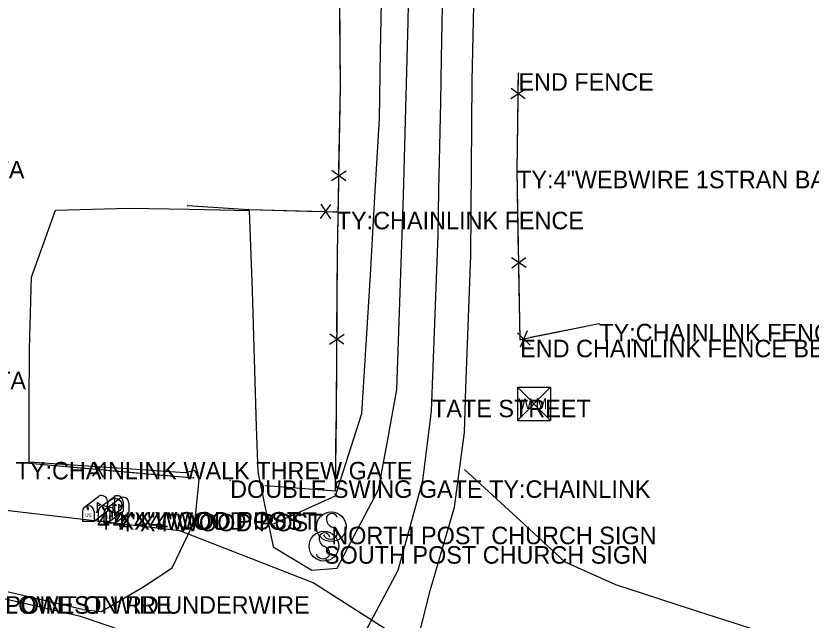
# Model space of a CAD drawing. Extents: x 1050807 to 1053552, y 395828 to 398415.
# Drawn here: x 1051813.5 to 1052040.5, y 398068.8 to 398241.2 of the extents above; entities that cross this region are included whole.
import ezdxf

# ---------------------------------------------------------------- set-up
doc = ezdxf.new("R2010")
doc.units = 0
for name, color, linetype in [('S_BUILDING_ANNOT', 7, 'Continuous'), ('S_EDGE_PAVEMENT', 7, 'Continuous'), ('S_ELECTRIC_UTILITIES_ANNOT', 7, 'Continuous'), ('S_FENCE', 7, 'Continuous'), ('S_FENCE_ANNOT', 7, 'Continuous'), ('S_GATE_ANNOT', 7, 'Continuous'), ('S_GRAVEL_ROAD', 7, 'Continuous'), ('S_MAILBOX', 7, 'Continuous'), ('S_MAILBOX_ANNOT', 7, 'Continuous'), ('S_MSC_PT_SYM', 7, 'Continuous'), ('S_PAVEMENT_CROWN', 7, 'Continuous'), ('S_SHOULDER', 7, 'Continuous'), ('S_SIGN', 7, 'Continuous'), ('S_SIGN_ANNOT', 7, 'Continuous'), ('S_SURVEY_TEXT_ANNOT', 7, 'Continuous'), ('S_UTILITY_POLE', 7, 'Continuous'), ('S_UTL_PT_SYM', 7, 'Continuous'), ('S_WATER_UTILITIES', 7, 'Continuous')]:
    doc.layers.add(name, color=color, linetype=linetype)

msp = doc.modelspace()

# ---------------------------------------------------------------- linework, layer by layer
at = {"layer": 'S_EDGE_PAVEMENT'}
for points in [[(1051934.63, 398023.1), (1051930.06, 398027.26), (1051929.8, 398038.82), (1051925.96, 398053.99), (1051931.83, 398077.54), (1051938.69, 398100.99), (1051941.54, 398122.27), (1051942, 398134.91), (1051942.46, 398147.55), (1051942.93, 398160.19), (1051943.39, 398172.83), (1051943.59, 398197.73), (1051943.79, 398222.64), (1051944.04, 398235.63), (1051944.3, 398248.63), (1051944.55, 398261.62), (1051944.81, 398274.62), (1051944.95, 398287.8), (1051945.09, 398300.98), (1051945.24, 398314.17), (1051945.38, 398327.35), (1051945.7, 398344.1), (1051946.02, 398360.85)], [(1051832.59, 398071.82), (1051837.82, 398071.26), (1051849.77, 398078.16), (1051858.11, 398083.68), (1051864.69, 398097.36), (1051865.79, 398108.89), (1051864.58, 398111.44), (1051861.82, 398110.77), (1051839.56, 398112.3), (1051817.29, 398113.82), (1051817.34, 398129.93), (1051817.39, 398146.04), (1051817.93, 398166.59), (1051824.83, 398185.78), (1051845.77, 398186.36), (1051862.94, 398186), (1051880.11, 398185.63), (1051880.93, 398162.71), (1051881.33, 398149.8), (1051881.73, 398136.89), (1051882.13, 398123.97), (1051882.54, 398111.06), (1051886.98, 398089.68), (1051898.02, 398083.02), (1051905.24, 398083.58), (1051911.15, 398094.8), (1051917.06, 398106.02), (1051919.65, 398120.3), (1051922.25, 398134.57), (1051922.72, 398148.4), (1051923.19, 398162.24), (1051923.67, 398176.07), (1051924.14, 398189.9), (1051924.81, 398214.72), (1051925.48, 398239.54), (1051926, 398264.45)], [(1051844.58, 398065.54), (1051831.93, 398069.76), (1051807.96, 398075.33)]]:
    msp.add_lwpolyline(points, dxfattribs=at)
at = {"layer": 'S_FENCE'}
for p, q in [((1051906.18, 398220.91), (1051905.81, 398265.54)), ((1051956.61, 398197), (1051956.97, 398224.83)), ((1051905.3, 398173.58), (1051906.18, 398220.91)), ((1051954.83, 398217.59), (1051958.96, 398220.41)), ((1051954.83, 398217.59), (1051958.96, 398220.41)), ((1051958.92, 398217.54), (1051954.86, 398220.46)), ((1051958.92, 398217.54), (1051954.86, 398220.46)), ((1051903.64, 398194.18), (1051907.79, 398196.97)), ((1051903.64, 398194.18), (1051907.79, 398196.97)), ((1051907.73, 398194.1), (1051903.69, 398197.05)), ((1051907.73, 398194.1), (1051903.69, 398197.05)), ((1051957.47, 398148.77), (1051956.61, 398197)), ((1051862.46, 398187.07), (1051879.97, 398185.9)), ((1051900.48, 398183.35), (1051903.45, 398187.38)), ((1051900.48, 398183.35), (1051903.45, 398187.38)), ((1051900.58, 398187.45), (1051903.35, 398183.28)), ((1051900.58, 398187.45), (1051903.35, 398183.28)), ((1051879.97, 398185.9), (1051905.1, 398185.29)), ((1051905, 398126.9), (1051905.3, 398173.58)), ((1051959.15, 398169.37), (1051955, 398172.16)), ((1051959.15, 398169.37), (1051955, 398172.16)), ((1051955.06, 398169.3), (1051959.1, 398172.24)), ((1051955.06, 398169.3), (1051959.1, 398172.24)), ((1051980.06, 398153.3), (1051957.47, 398148.77)), ((1051903.08, 398147.48), (1051907.2, 398150.32)), ((1051903.08, 398147.48), (1051907.2, 398150.32)), ((1051907.18, 398147.46), (1051903.1, 398150.35)), ((1051907.18, 398147.46), (1051903.1, 398150.35)), ((1051960.3, 398147.25), (1051956.69, 398150.7)), ((1051960.3, 398147.25), (1051956.69, 398150.7)), ((1051959.5, 398151.27), (1051957.49, 398146.69)), ((1051959.5, 398151.27), (1051957.49, 398146.69)), ((1051904.76, 398105.62), (1051905, 398126.9)), ((1051835.88, 398113.92), (1051838.38, 398109.59)), ((1051835.88, 398113.92), (1051838.38, 398109.59)), ((1051815.22, 398113.69), (1051864.2, 398109.36)), ((1051835.52, 398109.84), (1051838.74, 398113.67)), ((1051835.52, 398109.84), (1051838.74, 398113.67)), ((1051884.8, 398107.15), (1051904.76, 398105.62))]:
    msp.add_line(p, q, dxfattribs=at)
for points in [[(1051906.18, 398220.91), (1051906.01, 398240.91)], [(1051906.18, 398220.91), (1051906.01, 398240.91)], [(1051956.92, 398221), (1051956.97, 398224.83)], [(1051956.92, 398221), (1051956.97, 398224.83)], [(1051905.75, 398197.58), (1051906.18, 398220.91)], [(1051905.75, 398197.58), (1051906.18, 398220.91)], [(1051956.61, 398197), (1051956.87, 398217)], [(1051956.61, 398197), (1051956.87, 398217)], [(1051957.04, 398172.77), (1051956.61, 398197)], [(1051957.04, 398172.77), (1051956.61, 398197)], [(1051905.3, 398173.58), (1051905.67, 398193.58)], [(1051905.3, 398173.58), (1051905.67, 398193.58)], [(1051862.46, 398187.07), (1051879.97, 398185.9)], [(1051862.46, 398187.07), (1051879.97, 398185.9)], [(1051879.97, 398185.9), (1051899.97, 398185.41)], [(1051879.97, 398185.9), (1051899.97, 398185.41)], [(1051903.96, 398185.31), (1051905.1, 398185.29)], [(1051903.96, 398185.31), (1051905.1, 398185.29)], [(1051905.15, 398150.9), (1051905.3, 398173.58)], [(1051905.15, 398150.9), (1051905.3, 398173.58)], [(1051957.47, 398148.77), (1051957.11, 398168.77)], [(1051957.47, 398148.77), (1051957.11, 398168.77)], [(1051980.06, 398153.3), (1051960.45, 398149.37)], [(1051980.06, 398153.3), (1051960.45, 398149.37)], [(1051905, 398126.9), (1051905.13, 398146.9)], [(1051905, 398126.9), (1051905.13, 398146.9)], [(1051904.76, 398105.62), (1051904.98, 398125.62)], [(1051904.76, 398105.62), (1051904.98, 398125.62)], [(1051815.22, 398113.69), (1051835.14, 398111.93)], [(1051815.22, 398113.69), (1051835.14, 398111.93)], [(1051839.12, 398111.58), (1051864.2, 398109.36)], [(1051839.12, 398111.58), (1051864.2, 398109.36)], [(1051884.8, 398107.15), (1051904.72, 398105.62)], [(1051884.8, 398107.15), (1051904.72, 398105.62)]]:
    msp.add_lwpolyline(points, dxfattribs=at)
at = {"layer": 'S_GRAVEL_ROAD'}
for points in [[(1051920.21, 398327.61), (1051919.09, 398311.82), (1051919.87, 398290.35), (1051918.86, 398270.17), (1051917.86, 398250), (1051917.52, 398230.91), (1051917.19, 398211.82), (1051915.93, 398189.54), (1051914.68, 398167.26), (1051913.41, 398147.42), (1051912.15, 398127.59), (1051904.68, 398104.16), (1051886.45, 398095.96)], [(1051941.6, 398111.76), (1051957.6, 398097.06), (1051970.21, 398085.36), (1051984.67, 398078.88), (1052006.03, 398072.02), (1052027.38, 398065.17), (1052046.41, 398052.69), (1052065.44, 398040.21), (1052080.08, 398025.28), (1052094.72, 398010.35), (1052105.27, 397991.93), (1052108.07, 397979.7), (1052110.87, 397967.48), (1052113.67, 397955.25), (1052116.48, 397943.02), (1052122.03, 397920.87), (1052127.57, 397898.72), (1052130.86, 397881.88), (1052134.15, 397865.05), (1052139.91, 397846.05), (1052147.47, 397834.83)]]:
    msp.add_lwpolyline(points, dxfattribs=at)
at = {"layer": 'S_MAILBOX'}
for p, q in [((1051833.08, 398101.02), (1051837.21, 398104.13)), ((1051837.55, 398100.97), (1051841.69, 398104.07)), ((1051839.19, 398100.54), (1051843.33, 398103.64)), ((1051839.64, 398102.66), (1051839.64, 398099.94)), ((1051844.12, 398102.6), (1051844.12, 398099.89)), ((1051836.69, 398102.31), (1051836.69, 398099.6)), ((1051841.17, 398102.25), (1051841.17, 398099.54)), ((1051842.81, 398101.82), (1051842.81, 398099.11)), ((1051845.76, 398102.17), (1051845.76, 398099.46)), ((1051832.52, 398099.75), (1051832.52, 398097.03)), ((1051835.85, 398097.03), (1051839.64, 398099.94)), ((1051835.85, 398099.75), (1051835.85, 398097.03)), ((1051837, 398099.69), (1051837, 398096.98)), ((1051838.64, 398099.26), (1051838.64, 398096.55)), ((1051840.32, 398096.98), (1051844.12, 398099.89)), ((1051840.32, 398099.69), (1051840.32, 398096.98)), ((1051841.96, 398096.55), (1051845.76, 398099.46)), ((1051841.96, 398099.26), (1051841.96, 398096.55)), ((1051832.52, 398097.03), (1051835.85, 398097.03)), ((1051837, 398096.98), (1051840.32, 398096.98)), ((1051838.64, 398096.55), (1051841.96, 398096.55))]:
    msp.add_line(p, q, dxfattribs=at)
for points in [[(1051833.71, 398100.86), (1051833.93, 398100.73), (1051833.93, 398100.34), (1051834.23, 398100.34), (1051834.23, 398100.7), (1051834.04, 398100.95), (1051833.71, 398100.89)], [(1051836.69, 398102.31), (1051837.8, 398101.65), (1051836.69, 398101.3)], [(1051838.18, 398100.81), (1051838.4, 398100.67), (1051838.4, 398100.28), (1051838.71, 398100.28), (1051838.71, 398100.64), (1051838.51, 398100.89), (1051838.18, 398100.83)], [(1051839.82, 398100.38), (1051840.04, 398100.24), (1051840.04, 398099.85), (1051840.35, 398099.85), (1051840.35, 398100.21), (1051840.15, 398100.46), (1051839.82, 398100.4)], [(1051841.17, 398102.25), (1051842.27, 398101.59), (1051841.17, 398101.24)], [(1051842.81, 398101.82), (1051843.91, 398101.16), (1051842.81, 398100.81)]]:
    msp.add_lwpolyline(points, dxfattribs=at)
for centre, end in [((1051837.98, 398102.66), 117.5718), ((1051842.45, 398102.6), 117.5718), ((1051844.09, 398102.17), 117.5718), ((1051834.18, 398099.75), 180), ((1051838.66, 398099.69), 180), ((1051840.3, 398099.26), 180)]:
    msp.add_arc(centre, 1.66, 0, end, dxfattribs=at)
for centre in [(1051836.69, 398099.6), (1051841.17, 398099.54), (1051842.81, 398099.11)]:
    msp.add_ellipse(centre, major_axis=(0.145, 0.132), ratio=0.564646, dxfattribs=at)
at = {"layer": 'S_MSC_PT_SYM'}
for points in [[(1051956.97, 398224.83), (1051956.97, 398224.88), (1051956.97, 398224.83), (1051956.92, 398224.83), (1051956.97, 398224.83), (1051956.97, 398224.78), (1051956.97, 398224.83), (1051957.02, 398224.83)], [(1051906.18, 398220.91), (1051906.18, 398220.96), (1051906.18, 398220.91), (1051906.13, 398220.91), (1051906.18, 398220.91), (1051906.18, 398220.86), (1051906.18, 398220.91), (1051906.23, 398220.91)], [(1051956.61, 398197), (1051956.61, 398197.05), (1051956.61, 398197), (1051956.56, 398197), (1051956.61, 398197), (1051956.61, 398196.95), (1051956.61, 398197), (1051956.66, 398197)], [(1051862.46, 398187.07), (1051862.46, 398187.12), (1051862.46, 398187.07), (1051862.41, 398187.07), (1051862.46, 398187.07), (1051862.46, 398187.02), (1051862.46, 398187.07), (1051862.51, 398187.07)], [(1051879.97, 398185.9), (1051879.97, 398185.95), (1051879.97, 398185.9), (1051879.92, 398185.9), (1051879.97, 398185.9), (1051879.97, 398185.85), (1051879.97, 398185.9), (1051880.02, 398185.9)], [(1051905.1, 398185.29), (1051905.1, 398185.34), (1051905.1, 398185.29), (1051905.05, 398185.29), (1051905.1, 398185.29), (1051905.1, 398185.24), (1051905.1, 398185.29), (1051905.15, 398185.29)], [(1051905.3, 398173.58), (1051905.3, 398173.63), (1051905.3, 398173.58), (1051905.25, 398173.58), (1051905.3, 398173.58), (1051905.3, 398173.53), (1051905.3, 398173.58), (1051905.35, 398173.58)], [(1051980.06, 398153.3), (1051980.06, 398153.35), (1051980.06, 398153.3), (1051980.01, 398153.3), (1051980.06, 398153.3), (1051980.06, 398153.25), (1051980.06, 398153.3), (1051980.11, 398153.3)], [(1051957.47, 398148.77), (1051957.47, 398148.82), (1051957.47, 398148.77), (1051957.42, 398148.77), (1051957.47, 398148.77), (1051957.47, 398148.72), (1051957.47, 398148.77), (1051957.52, 398148.77)], [(1051932.31, 398131.64), (1051932.31, 398131.69), (1051932.31, 398131.64), (1051932.26, 398131.64), (1051932.31, 398131.64), (1051932.31, 398131.59), (1051932.31, 398131.64), (1051932.36, 398131.64)], [(1051905, 398126.9), (1051905, 398126.95), (1051905, 398126.9), (1051904.95, 398126.9), (1051905, 398126.9), (1051905, 398126.85), (1051905, 398126.9), (1051905.05, 398126.9)], [(1051815.22, 398113.69), (1051815.22, 398113.74), (1051815.22, 398113.69), (1051815.17, 398113.69), (1051815.22, 398113.69), (1051815.22, 398113.64), (1051815.22, 398113.69), (1051815.27, 398113.69)], [(1051864.2, 398109.36), (1051864.2, 398109.41), (1051864.2, 398109.36), (1051864.15, 398109.36), (1051864.2, 398109.36), (1051864.2, 398109.31), (1051864.2, 398109.36), (1051864.25, 398109.36)], [(1051874.67, 398108.64), (1051874.67, 398108.69), (1051874.67, 398108.64), (1051874.62, 398108.64), (1051874.67, 398108.64), (1051874.67, 398108.59), (1051874.67, 398108.64), (1051874.72, 398108.64)], [(1051884.8, 398107.15), (1051884.8, 398107.2), (1051884.8, 398107.15), (1051884.75, 398107.15), (1051884.8, 398107.15), (1051884.8, 398107.1), (1051884.8, 398107.15), (1051884.85, 398107.15)], [(1051904.76, 398105.62), (1051904.76, 398105.67), (1051904.76, 398105.62), (1051904.71, 398105.62), (1051904.76, 398105.62), (1051904.76, 398105.57), (1051904.76, 398105.62), (1051904.81, 398105.62)]]:
    msp.add_lwpolyline(points, dxfattribs=at)
at = {"layer": 'S_PAVEMENT_CROWN'}
msp.add_lwpolyline([(1051911.73, 398062.49), (1051922.6, 398083.01), (1051926.16, 398095.8), (1051929.71, 398108.59), (1051932.19, 398128.36), (1051932.65, 398140.95), (1051933.12, 398153.54), (1051933.58, 398166.13), (1051934.04, 398178.71), (1051934.3, 398191.33), (1051934.55, 398203.94), (1051934.81, 398216.55), (1051935.06, 398229.16), (1051935.51, 398253.78), (1051935.96, 398278.4), (1051936.1, 398291.5), (1051936.24, 398304.61), (1051936.39, 398317.72), (1051936.53, 398330.82), (1051937.06, 398346.12), (1051937.6, 398361.41)], dxfattribs=at)
at = {"layer": 'S_SHOULDER'}
msp.add_lwpolyline([(1051832.54, 398071.82), (1051808.46, 398077.37), (1051784.37, 398082.92), (1051763.72, 398085.7), (1051743.06, 398088.49), (1051728.32, 398089.56), (1051713.58, 398090.62)], dxfattribs=at)
at = {"layer": 'S_SIGN'}
for centre in [(1051903.54, 398095.41), (1051901.46, 398089.86)]:
    msp.add_circle(centre, 4.24, dxfattribs=at)
for centre, radius, start, end in [((1051904.71, 398097.66), 2.55, 167.1196, 241.9813), ((1051903.67, 398097.56), 1.62, 16.5258, 156.8957), ((1051901.58, 398092.01), 1.62, 16.5258, 156.8957), ((1051902.84, 398093.13), 2.38, 358.6529, 73.7063), ((1051902.62, 398092.11), 2.55, 167.1196, 241.9813), ((1051903.28, 398094.01), 2.17, 204.641, 335.359), ((1051900.76, 398087.58), 2.38, 358.6529, 73.7063), ((1051901.2, 398088.46), 2.17, 204.641, 335.359)]:
    msp.add_arc(centre, radius, start, end, dxfattribs=at)
at = {"layer": 'S_UTILITY_POLE'}
msp.add_line((1051841.75, 398098.55), (1051841.75, 398104.34), dxfattribs=at)
msp.add_circle((1051841.75, 398101.48), 2.05, dxfattribs=at)
at = {"layer": 'S_UTL_PT_SYM'}
for points in [[(1051860.36, 398094.28), (1051860.36, 398094.33), (1051860.36, 398094.28), (1051860.31, 398094.28), (1051860.36, 398094.28), (1051860.36, 398094.23), (1051860.36, 398094.28), (1051860.41, 398094.28)], [(1051898.42, 398079.37), (1051898.42, 398079.42), (1051898.42, 398079.37), (1051898.37, 398079.37), (1051898.42, 398079.37), (1051898.42, 398079.32), (1051898.42, 398079.37), (1051898.47, 398079.37)]]:
    msp.add_lwpolyline(points, dxfattribs=at)
at = {"layer": 'S_WATER_UTILITIES'}
for p, q in [((1051956.76, 398135.23), (1051966.1, 398135.23)), ((1051956.76, 398135.23), (1051956.76, 398125.74)), ((1051956.76, 398135.23), (1051966.1, 398125.74)), ((1051966.1, 398135.23), (1051956.76, 398125.74)), ((1051966.1, 398135.23), (1051966.1, 398125.74)), ((1051956.76, 398125.74), (1051966.1, 398125.74)), ((1051860.36, 398094.28), (1051802.09, 398101.03)), ((1051898.42, 398079.37), (1051860.36, 398094.28)), ((1051937.42, 398054.58), (1051898.42, 398079.37))]:
    msp.add_line(p, q, dxfattribs=at)

# ---------------------------------------------------------------- texts
at = {"layer": 'S_BUILDING_ANNOT'}
for s, p in [('COR PAVILLION TA', (1051754.28, 398194.8)), ('PAVILLION PBH TA', (1051755.84, 398134.64))]:
    msp.add_text(s, height=5, dxfattribs=at).set_placement(p)
at = {"layer": 'S_ELECTRIC_UTILITIES_ANNOT'}
msp.add_text('LOWEST WIRE', height=5, dxfattribs=at).set_placement((1051810.46, 398070.58))
at = {"layer": 'S_FENCE_ANNOT'}
for s, p in [('END FENCE', (1051956.97, 398219.83)), ('TY:4"WEBWIRE 1STRAN BARBWIRE', (1051956.61, 398192)), ('TY:CHAINLINK FENCE', (1051905.1, 398180.29)), ('TY:CHAINLINK FENCE', (1051980.06, 398148.3)), ('END CHAINLINK FENCE BEGIN 4"WEB', (1051957.47, 398143.77))]:
    msp.add_text(s, height=5, dxfattribs=at).set_placement(p)
at = {"layer": 'S_GATE_ANNOT'}
for s, p in [('TY:CHAINLINK WALK THREW GATE', (1051813.41, 398108.91)), ('DOUBLE SWING GATE TY:CHAINLINK', (1051874.67, 398103.64))]:
    msp.add_text(s, height=5, dxfattribs=at).set_placement(p)
at = {"layer": 'S_MAILBOX'}
for p in [(1051833.29, 398098.23), (1051837.76, 398098.17), (1051839.4, 398097.74)]:
    msp.add_text('US', height=0.96, dxfattribs=at).set_placement(p)
at = {"layer": 'S_MAILBOX_ANNOT'}
for p in [(1051836.69, 398094.6), (1051841.17, 398094.54), (1051842.81, 398094.11)]:
    msp.add_text('4"X4"WOOD POST', height=5, dxfattribs=at).set_placement(p)
at = {"layer": 'S_SIGN_ANNOT'}
for s, p in [('NORTH POST CHURCH SIGN', (1051903.54, 398090.41)), ('SOUTH POST CHURCH SIGN', (1051901.46, 398084.86))]:
    msp.add_text(s, height=5, dxfattribs=at).set_placement(p)
at = {"layer": 'S_SURVEY_TEXT_ANNOT'}
for s, p in [('TATE STREET', (1051932.31, 398126.64)), ('POINT ON RD UNDERWIRE', (1051810.46, 398070.58))]:
    msp.add_text(s, height=5, dxfattribs=at).set_placement(p)
at = {"layer": 'S_WATER_UTILITIES'}
msp.add_text('W M', height=3, dxfattribs=at).set_placement((1051956.97, 398129))

doc.saveas('drawing.dxf')
